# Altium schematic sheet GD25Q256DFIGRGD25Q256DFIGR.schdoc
size 127 x 101 mm
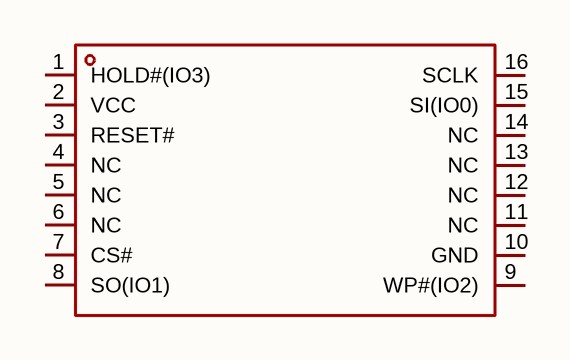
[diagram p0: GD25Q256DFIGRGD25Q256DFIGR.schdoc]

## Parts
U?  gd25q256dfigr  [SOP-16_L10.3-W7.5-P1.27-LS10.4-BL]  (value not drawn)

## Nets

Not connected (* = marked no-connect by the designer): U? 1(HOLD#(IO3)) 2(VCC) 3(RESET#) 4(NC) 5(NC) 6(NC) 7(CS#) 8(SO(IO1)) 9(WP#(IO2)) 10(GND) 11(NC) 12(NC) 13(NC) 14(NC) 15(SI(IO0)) 16(SCLK)

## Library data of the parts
U? = gd25q256dfigr: 接口类型:SPI;存储容量:256Mbit;时钟频率(fc):104MHz;; Manufacturer: GigaDevice(兆易创新); AddInBom: yes; ModelId: 9d9a18a1b385474aa237d069b9ffbb63; ModelName: SOP-16_L10.3-W7.5-H2.1-LS10.0-P1.27; ModelTransform: 405.511,393.7,0,0,0,0,0,0,0; Interface: SPI; Clock Frequency: 104MHz; Voltage - Supply: 2.7V~3.6V; Standby Supply Current: 12uA; Program / Erase Cycles: 100000次; Page Programming Time (Tpp): 400us; Data Retention - TDR (Year): 20年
